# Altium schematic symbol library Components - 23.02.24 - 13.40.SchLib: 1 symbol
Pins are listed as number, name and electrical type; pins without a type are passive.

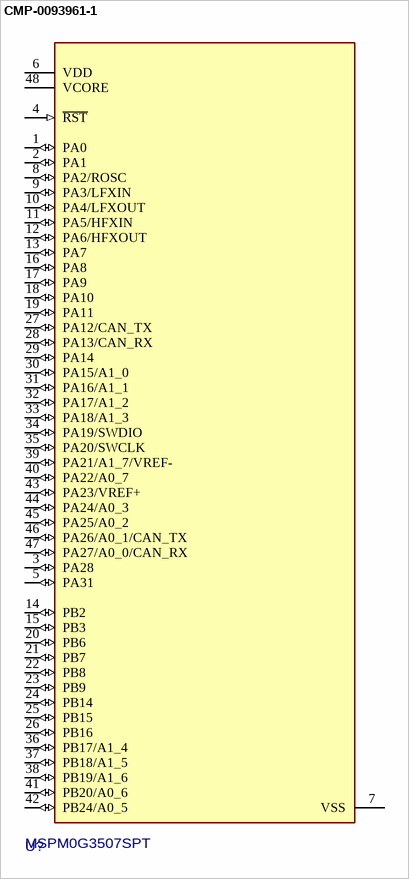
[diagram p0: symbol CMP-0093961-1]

## CMP-0093961-1
designator U?, comment MSPM0G3507SPT
Mixed-Signal Microcontrollers with CAN-FD Interface ARM Cortex-M0+ 32bits 128KB Flash 32KB RAM LQFP48 AEC Q-200 Grade 1 80MHz; Manufacturer: Texas Instruments; Number Of I/Os: 44; Interface: I2C,SPI,UART,CAN,LIN,IrDA,SMBus; Number Of I2C Channels: 2; AEC Grade: Grade 1; TaMin_C: -40°C; Number Of Adc Channels: 15; Standoff Height: 0.05mm; Ram Size: 32KBytes; Number Of Pwm Channels: 20; Min Supply Voltage: 1.62V; AEC Qualified: Yes; Number Of Timers/Counters: 6; SizeZ_mm: 1.6mm; Number Of Cores: 1; TaMax_C: +125°C; TJmax_C: +130°C; Memory Size: 128KBytes; Max Supply Voltage: 3.6V; Number Of Uart Channels: 4
footprint PT0048A-IPC_B
footprint PT0048A-IPC_A
footprint PT0048A-IPC_C
footprint PT0048A-MFG
pins: 1 PA0 (io), 2 PA1 (io), 3 PA28 (io), 4 ~{RST} (in), 5 PA31 (io), 6 VDD (power), 7 VSS (power), 8 PA2/ROSC (io), 9 PA3/LFXIN (io), 10 PA4/LFXOUT (io), 11 PA5/HFXIN (io), 12 PA6/HFXOUT (io), 13 PA7 (io), 14 PB2 (io), 15 PB3 (io), 16 PA8 (io), 17 PA9 (io), 18 PA10 (io), 19 PA11 (io), 20 PB6 (io), 21 PB7 (io), 22 PB8 (io), 23 PB9 (io), 24 PB14 (io), 25 PB15 (io), 26 PB16 (io), 27 PA12/CAN_TX (io), 28 PA13/CAN_RX (io), 29 PA14 (io), 30 PA15/A1_0 (io), 31 PA16/A1_1 (io), 32 PA17/A1_2 (io), 33 PA18/A1_3 (io), 34 PA19/SWDIO (io), 35 PA20/SWCLK (io), 36 PB17/A1_4 (io), 37 PB18/A1_5 (io), 38 PB19/A1_6 (io), 39 PA21/A1_7/VREF- (io), 40 PA22/A0_7 (io), 41 PB20/A0_6 (io), 42 PB24/A0_5 (io), 43 PA23/VREF+ (io), 44 PA24/A0_3 (io), 45 PA25/A0_2 (io), 46 PA26/A0_1/CAN_TX (io), 47 PA27/A0_0/CAN_RX (io), 48 VCORE (power)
